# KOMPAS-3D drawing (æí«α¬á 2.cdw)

Referenced files: СБ-1003.cdw
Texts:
  Редуктор цилиндрический Сборочный чертёж
  Noncommercial version
  Технические характеристики
  1. Мощность на тихоходном валу N  = 0,799 кВт
  2. Крутящий момент на тихоходном валу Т = 114 Н*м
  3. Частота вращения тихоходного вала n = 67 об/мин
  4. Передаточное отношение Uобщ = 7,056
  быстроходной ступени Uб = 3,15
  тихоходной ступени Uт = 2,24
  5. Режим работы: средний нормальный
  6. Срок службы L = 7884 часа.
  Технические требования
  1.  Перед сборкой редуктора детали очистить от окалины и стружки.
  2. Редуктор заправить обкатной смесью или маслом И-30А по
  ГОСТ 20799-75* и обкатать на стенде. Время обкатки 40 мин.
  После обкатки масло должно быть смыто.
  3. При обкатке редуктора допускаются изменения в зубчатых
  зацеплениях.
  4. При обкатке редуктора не должно быть стуков и заедания
  зубчатого зацепления, просачивания смазки через уплотнения,
  прокладки, пробки.
  5. Смазка подшипников ВНИИ НП-274 по ГОСТ 19337-73.
  Шпонка 12 х 8 х 56 ГОСТ 23360-78
  Шпонка
  ГОСТ
  Шпонка 8 х 7 х 56 ГОСТ 23360-78
  Шпонка 14 х 9 х 90 ГОСТ 23360-78
  Болт М3 х 16 ГОСТ 7805-70
  Болт
  Шпонка 8 х 7 х 50 ГОСТ 23360-78
  Шпонка 6 х 6 х 36 ГОСТ 23360-78
  Штифт 10 х 24 ГОСТ 3128-70
  Штифт
  Хим.Окс.прм
  Мaнжета 1-24 х 38-1 / 3 ГОСТ 8752-79
  Манжета
  Мaнжета
  Мaнжета 1-35 х 50-1 / 3 ГОСТ 8752-79
  Редуктор цилиндрический
  Сборочный чертёж
  ДГТУ
Dimensions and other numbers on the sheet: 22; 1; 2; 21; 23; 24; 25; 26; 27; 37; 34; 38; 39; 40; 41; 42; 43; 44; 45; 100; 90; 112; 30; 5; 6; 7; 9; 12; 11; 13; 14; 15; 17; 16; 28; 29; 32; 35; 36; 10; 31; 3; 33; 4; 8; 62; 55; 68; 206; 250; 182,5; 346; 60; 6 отв.; 204; 368; 422; 18; 150; 19; 20; 78; -6g; 70; 1:1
